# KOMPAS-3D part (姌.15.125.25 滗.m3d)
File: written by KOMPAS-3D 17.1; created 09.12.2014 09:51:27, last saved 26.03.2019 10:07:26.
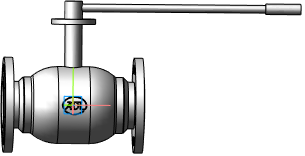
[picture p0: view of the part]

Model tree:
1. Операция без истории:5  (labels: Сталь 20  ГОСТ 1050-88)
